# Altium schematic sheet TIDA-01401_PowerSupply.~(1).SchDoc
size 431 x 279 mm; Date: Not shown in title block; ApprovedBy: Not shown in title block; CheckedBy: Not shown in title block; Author: Not shown in title block; CompanyName: Not shown in title block; Engineer: Not shown in title block; Organization: Not shown in title block; Address1: Not shown in title block; Address2: Not shown in title block; Address3: Not shown in title block; Address4: Not shown in title block; DocumentNumber: 1; Revision: Use project parameter SCH_Rev; SheetNumber: 2; SheetTotal: 3; PageSetup: Record=PageOptions¦CenterHorizontal=True¦CenterVertical=True¦PrintScale=1.00¦XCorrection=1.00¦YCorrection=1.00¦PrintKind=0¦BorderSize=5000000¦LeftOffset=0¦BottomOffset=0¦Orientation=2¦PaperLength=1000¦PaperWidth=1000¦Scale=100¦PaperSource=15¦PrintQuality=600¦MediaType=1¦DitherType=10¦PaperKind=Letter¦PrintScaleMode=1
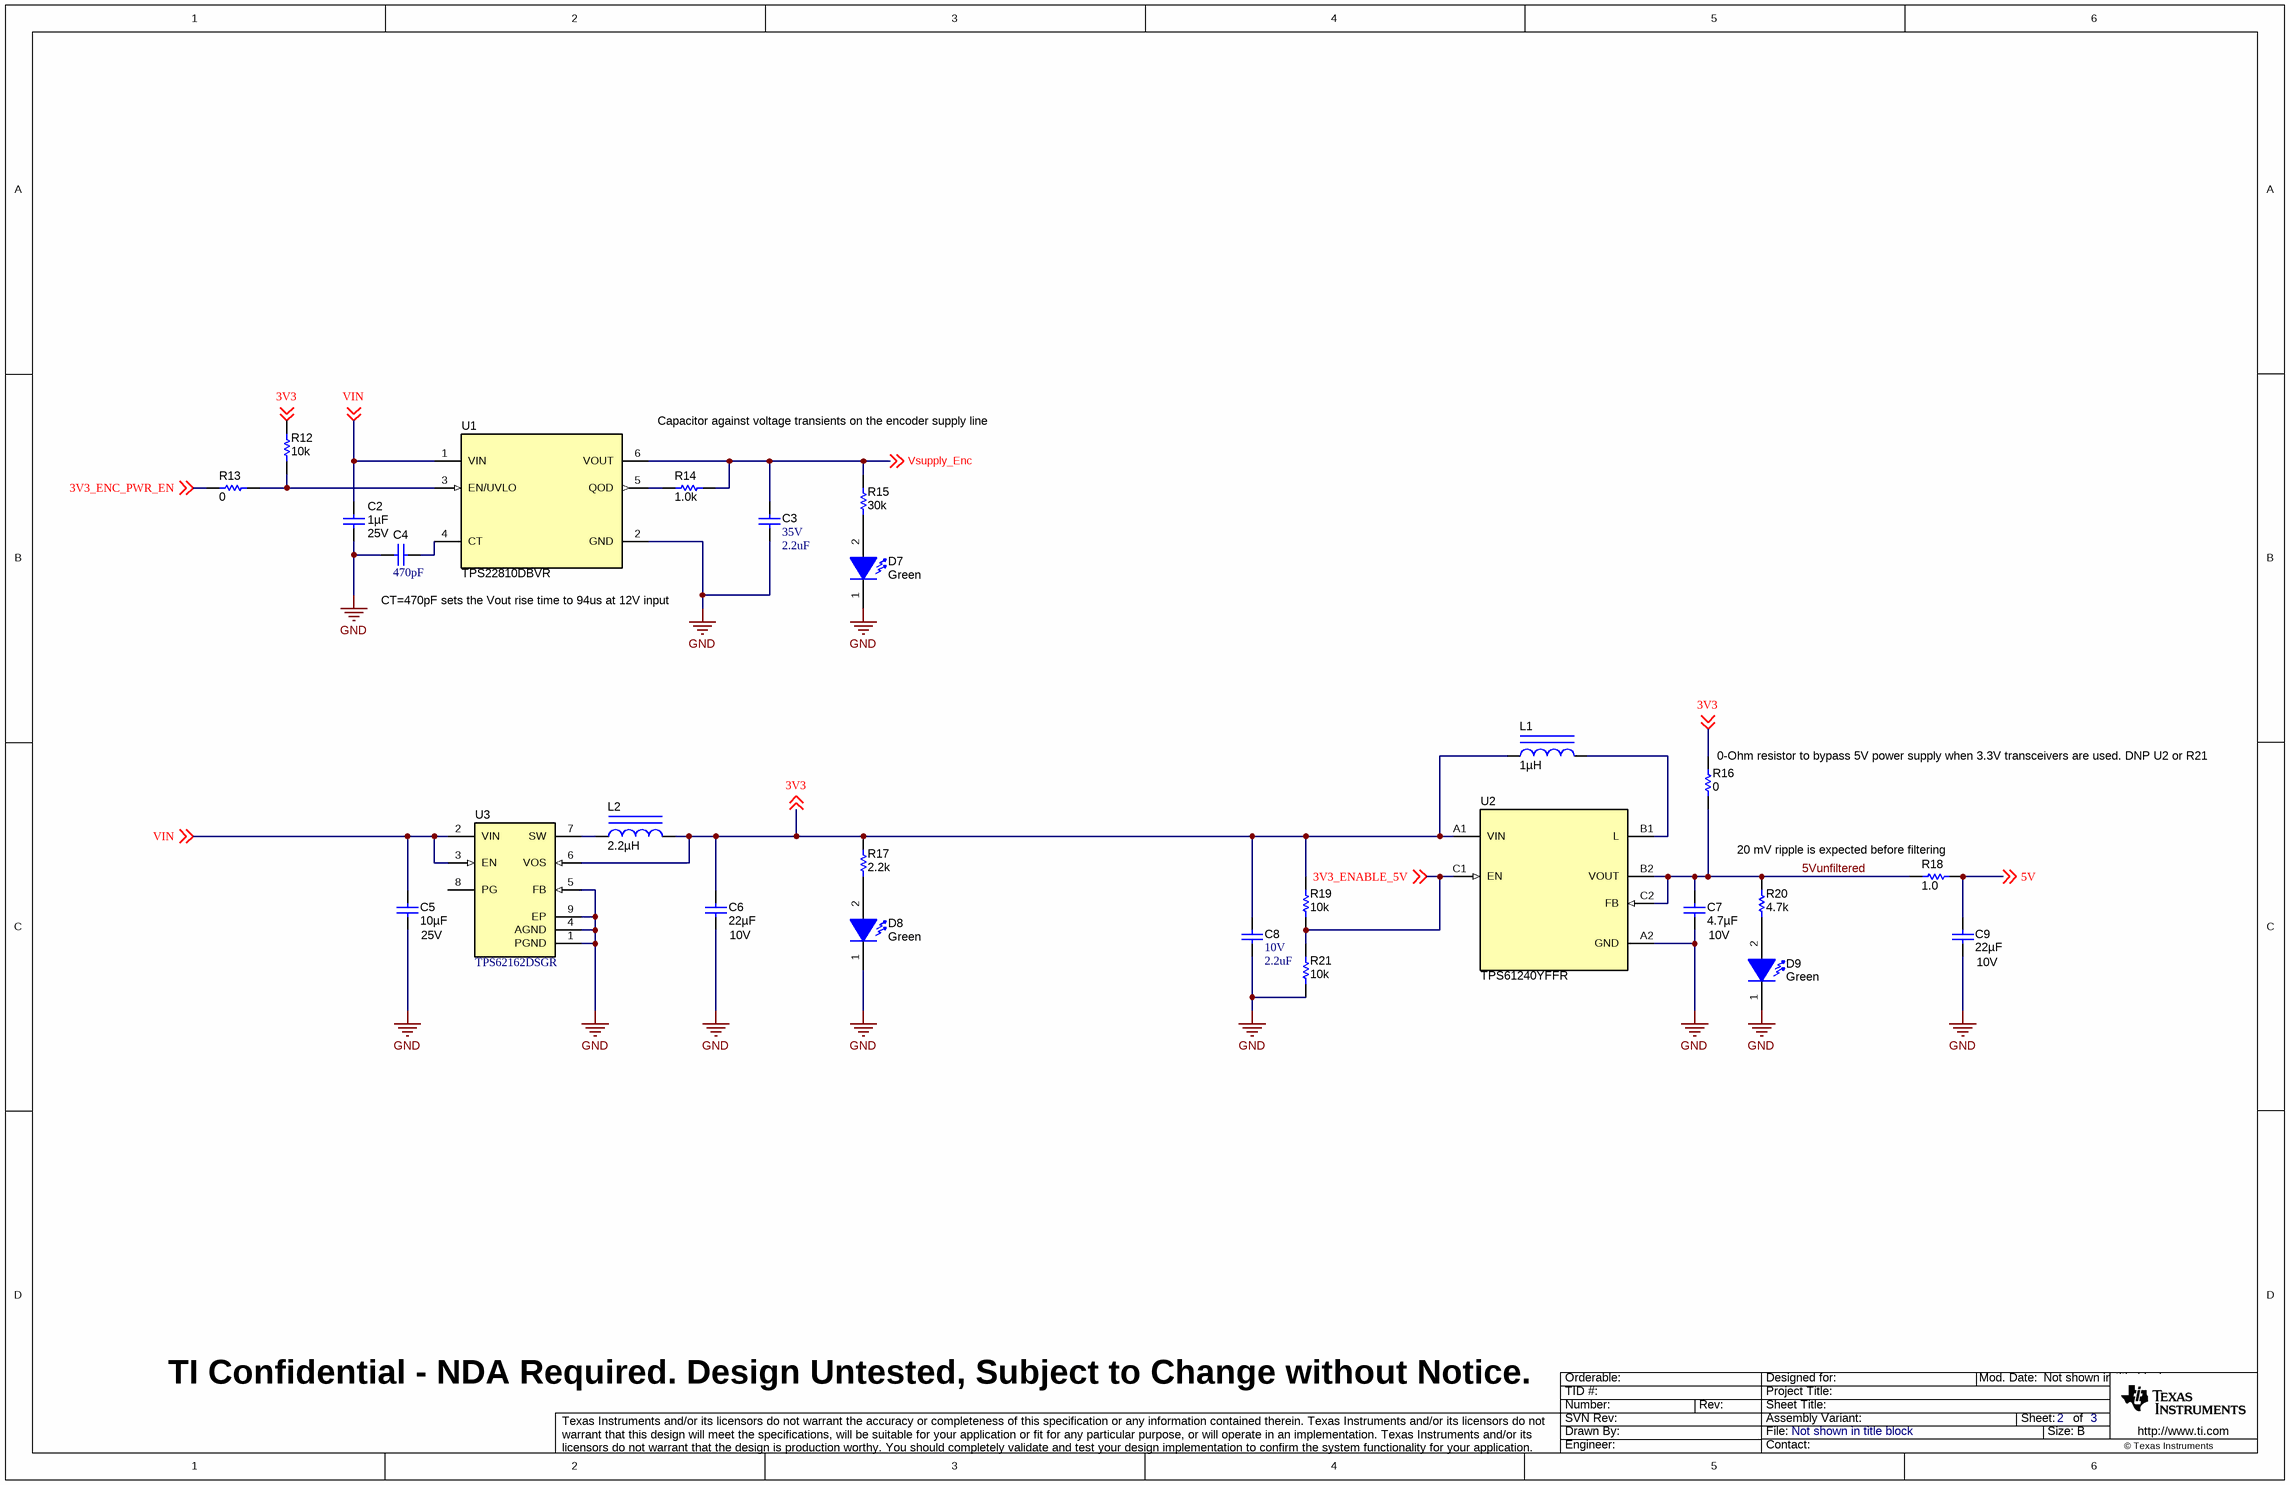
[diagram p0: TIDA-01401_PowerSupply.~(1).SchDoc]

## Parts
C2  ValueDisplayed: 1µF  Value2: 25V  [0603S]  (hidden comment: 885012206076)
C3  VDC_V: 35V  ValueDisplayed: 2.2uF  [0402_070]  (hidden comment: GRM155R6YA225ME11D)
C4  ValueDisplayed: 470pF  [0402S]  (hidden comment: GRM155R71H471KA01D)
C5  ValueDisplayed: 10µF  Value2: 25V  [0603S]  (hidden comment: C1608X5R1E106M080AC)
C6  ValueDisplayed: 22µF  Value2: 10V  [0603S]  (hidden comment: GRM187R61A226ME15D)
C7  ValueDisplayed: 4.7µF  Value2: 10V  [0402S]  (hidden comment: C1005X5R1A475K050BC)
C8  VDC_V: 10V  ValueDisplayed: 2.2uF  [0402S]  (hidden comment: 885012105013)
C9  ValueDisplayed: 22µF  Value2: 10V  [0603S]  (hidden comment: GRM187R61A226ME15D)
D7  value Green  [WL-SMCW_GREEN]  (hidden comment: 150060GS75000)
D8  value Green  [WL-SMCW_GREEN]  (hidden comment: 150060GS75000)
D9  value Green  [WL-SMCW_GREEN]  (hidden comment: 150060GS75000)
L1  ValueDisplayed: 1µH  [WE-PMI-0805_1]  (hidden comment: 74479775210)
L2  ValueDisplayed: 2.2µH  [XFL3012]  (hidden comment: XFL3012-222MEB)
R12  ValueDisplayed: 10k  [0402]  (hidden comment: CRCW040210K0JNED)
R13  ValueDisplayed: 0  [0402]  (hidden comment: CRCW04020000Z0ED)
R14  ValueDisplayed: 1.0k  [0603S]  (hidden comment: CRCW06031K00JNEA)
R15  ValueDisplayed: 30k  [0402S]  (hidden comment: CRCW040230K0JNED)
R16  ValueDisplayed: 0  [0402]  (hidden comment: CRCW04020000Z0ED)
R17  ValueDisplayed: 2.2k  [0402S]  (hidden comment: CRCW04022K20JNED)
R18  ValueDisplayed: 1.0  [0603S]  (hidden comment: CRCW06031R00JNEA)
R19  ValueDisplayed: 10k  [0402]  (hidden comment: CRCW040210K0JNED)
R20  ValueDisplayed: 4.7k  [0402S]  (hidden comment: CRCW04024K70JNED)
R21  ValueDisplayed: 10k  [0402]  (hidden comment: CRCW040210K0JNED)
U1  TPS22810DBVR  [DBV0006A_N]
U2  TPS61240YFFR  [YFF0006AEAE]
U3  TPS62162DSGR  [DSG0008A]

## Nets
GND: C2.2 C3.2 C4.1 C5.2 C6.2 C7.2 C8.2 C9.2 D7.1(K) D8.1(K) D9.1(K) R21.1 U1.2(GND) U2.A2(GND) U3.1(PGND) U3.4(AGND) U3.5(FB) U3.9(EP)
3V3: C6.1 C8.1 L1.1 L2.2 R12.2 R16.2 R17.2 R19.2 U2.A1(VIN) U3.6(VOS) ; off-sheet 3V3
3V3_ENABLE_5V: R19.1 R21.2 U2.C1(EN) ; off-sheet 3V3_ENABLE_5V
3V3_ENC_PWR_EN: R13.1 ; off-sheet 3V3_ENC_PWR_EN
5V: C9.1 R18.2 ; off-sheet 5V
5Vunfiltered: C7.1 R16.1 R18.1 R20.2 U2.B2(VOUT) U2.C2(FB)
VIN: C2.1 C5.1 U1.1(VIN) U3.2(VIN) U3.3(EN) ; off-sheet VIN
Vsupply_Enc: C3.1 R14.2 R15.1 U1.6(VOUT) ; off-sheet Vsupply_Enc
NetC4_2: C4.2 U1.4(CT)
NetD7_2: D7.2(A) R15.2
NetD8_2: D8.2(A) R17.1
NetD9_2: D9.2(A) R20.1
NetL1_2: L1.2 U2.B1(L)
NetL2_1: L2.1 U3.7(SW)
NetR12_1: R12.1 R13.2 U1.3(EN/UVLO)
NetR14_1: R14.1 U1.5(QOD)

Not connected (* = marked no-connect by the designer): U3 8(PG)

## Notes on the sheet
- (near U1) Capacitor against voltage transients on the encoder supply line
- CT=470pF sets the Vout rise time to 94us at 12V input
- (near R16) 0-Ohm resistor to bypass 5V power supply when 3.3V transceivers are used. DNP U2 or R21
- 20 mV ripple is expected before filtering
- TI Confidential - NDA Required. Design Untested, Subject to Change without Notice.

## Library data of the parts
C2 = 885012206076: CAP, CERM, 1 µF, 25 V, +/- 10%, X7R, 0603; Manufacturer: Wurth Elektronik; Polarized: N; CompType: Capacitor; Value: 1uF; U/M: EA; Cap_F: 0.000001; Tolerance_%: 10; Value1: Unknown; VDC_V: 25; TaMin_C: -55; TaMax_C: 125; Cap_Case: 0603; SizeArea_mm2: 1.28; SizeAreaWB_mm2: 4.68; SizeX_mm: 1.6; SizeY_mm: 0.8; SizeZ_mm: 1; AEC Category: Q200
C3 = CMP-0006621-2: CAP, CERM, 2.2 uF, 35 V, +/- 20%, X5R, 0402; Manufacturer: MuRata; TaMin_C: -55°C; Polarized: N; SizeAreaWB_mm2: 3; Value1: Unknown; U/M: EA; Value: 2.2uF; TaMax_C: 85°C; SizeZ_mm: 0.7; SizeX_mm: 1; SizeY_mm: 0.5; Cap_Case: 0402; CompType: Capacitor; Cap_F: 2.2µF; AEC Category: Q200
C4 = CMP-0006691-2: CAP, CERM, 470 pF, 50 V, +/- 10%, X7R, 0402; Manufacturer: MuRata; TaMin_C: -55°C; Polarized: N; SizeAreaWB_mm2: 3; Value1: Unknown; U/M: EA; Value: 470pF; TaMax_C: 125°C; SizeZ_mm: 0.6; SizeX_mm: 1; SizeY_mm: 0.5; Cap_Case: 0402; Value2: 50V; CompType: Capacitor; AEC Category: Q200
C5 = C1608X5R1E106M080AC: CAP, CERM, 10 µF, 25 V, +/- 20%, X5R, 0603; Manufacturer: TDK; Polarized: N; CompType: Capacitor; Value: 10uF; U/M: EA; Cap_F: 0.00001; Tolerance_%: 20; ESR_ohm: 0.004639; Value1: 0.004639 ohm; VDC_V: 25; IRMS_A: 2.41407; TaMin_C: -55; TaMax_C: 85; Cap_Case: 0603; SizeArea_mm2: 1.28; SizeAreaWB_mm2: 4.68; SizeX_mm: 1.6; SizeY_mm: 0.8; SizeZ_mm: 1; AEC Category: Q200
C6 C9 = GRM187R61A226ME15D: CAP, CERM, 22 µF, 10 V, +/- 20%, X5R, 0603; Manufacturer: MuRata; Polarized: N; CompType: Capacitor; Value: 22uF; U/M: EA; Cap_F: 0.000022; Tolerance_%: 20; Value1: Unknown; VDC_V: 10; TaMin_C: -55; TaMax_C: 85; Cap_Case: 0603; SizeArea_mm2: 1.28; SizeAreaWB_mm2: 4.68; SizeX_mm: 1.6; SizeY_mm: 0.8; SizeZ_mm: 1; AEC Category: Q200
C7 = C1005X5R1A475K050BC: CAP, CERM, 4.7 µF, 10 V, +/- 10%, X5R, 0402; Manufacturer: TDK; Polarized: N; CompType: Capacitor; Value: 4.7uF; U/M: EA; Cap_F: 0.0000047; Tolerance_%: 10; ESR_ohm: 0.003417; Value1: 0.003417 ohm; IRMS_A: 2.7063; TaMin_C: -55; TaMax_C: 85; Cap_Case: 0402_065; SizeArea_mm2: 0.5; SizeAreaWB_mm2: 3; SizeX_mm: 1; SizeZ_mm: 0.65; AEC Category: Q200
C8 = CMP-0006222-2: CAP, CERM, 2.2 uF, 10 V, +/- 20%, X5R, 0402; Manufacturer: Wurth Elektronik; TaMin_C: -55°C; Polarized: N; SizeAreaWB_mm2: 3; Value1: Unknown; U/M: EA; Value: 2.2uF; TaMax_C: 85°C; SizeZ_mm: 0.6; SizeX_mm: 1; SizeY_mm: 0.5; Cap_Case: 0402; CompType: Capacitor; Cap_F: 2.2µF; AEC Category: Q200
D7-D9 = 150060GS75000: LED, Green, SMD; Manufacturer: Wurth Elektronik; Type: InGaN; Vf_V: 3.2; Value2: 3.2V; Io_A: 0.02; Tjmax_C: 85; Value1: W; Angle: 140; U/M: EA
L1 = 74479775210: Inductor, Shielded Drum Core, Metal Composite, 1 µH, 0.7 A, 0.1 ohm, SMD; Manufacturer: Wurth Elektronik; Value: 1uH; Ind_H: 1.0E-6; Imax_A: 0.7; Irms: 1.1A @ 40C rise; Isat: 0.7A @ 30% inductance drop; DCR_ohm: 0.1; Value1: 0.1 ohm; Value2: 0.7A; SizeAreaWB_mm2: 6.6; SizeArea_mm2: 2.4; SizeX_mm: 2; SizeY_mm: 1.2; SizeZ_mm: 1; AEC Category: Q200
L2 = XFL3012-222MEB: Inductor, Shielded, Composite, 2.2 µH, 1.6 A, 0.08 ohm, SMD; Manufacturer: Coilcraft; Value: 2.2uH; Ind_H: 2.2E-6; Imax_A: 1.6; Irms: 1.9A @ 40C rise; Isat: 1.6A @ 30% inductance drop; DCR_ohm: 0.08; Value2: 1.6A; SizeAreaWB_mm2: 16; SizeArea_mm2: 9; SizeX_mm: 3; SizeZ_mm: 1.2; AEC Category: Q200
R12 R19 R21 = CRCW040210K0JNED: RES, 10 k, 5%, 0.063 W, 0402; Manufacturer: Vishay-Dale; CompType: Resistor; Value: 10k; Res_ohm: 10000; Value_Code: 10k0; Tolerance_%: 5; Power_W: 0.063; Value2: 0.063W; VDC_V: 50; TempCo: 200 ppm/C; SizeArea_mm2: 0.5; SizeX_mm: 1; SizeZ_mm: 0.6; EIA_Code: E24; U/M: EA; AEC Category: Q200
R13 R16 = CRCW04020000Z0ED: RES, 0, 5%, 0.063 W, 0402; Manufacturer: Vishay-Dale; CompType: Resistor; Value: 0; Value_Code: 0000; Tolerance_%: 5; Power_W: 0.063; Value2: 0.063W; VDC_V: 50; TempCo: 200 ppm/C; SizeArea_mm2: 0.5; SizeX_mm: 1; SizeZ_mm: 0.6; EIA_Code: E24; U/M: EA; AEC Category: Q200
R14 = CRCW06031K00JNEA: RES, 1.0 k, 5%, 0.1 W, 0603; Manufacturer: Vishay-Dale; CompType: Resistor; Value: 1.0k; Res_ohm: 1000; Value_Code: 1k00; Tolerance_%: 5; Power_W: 0.1; Value2: 0.1W; VDC_V: 75; TempCo: 200 ppm/C; SizeArea_mm2: 1.28; SizeX_mm: 1.6; SizeY_mm: 0.8; SizeZ_mm: 1; EIA_Code: E24; U/M: EA; AEC Category: Q200
R15 = CRCW040230K0JNED: RES, 30 k, 5%, 0.063 W, 0402; Manufacturer: Vishay-Dale; CompType: Resistor; Value: 30k; Res_ohm: 30000; Value_Code: 30k0; Tolerance_%: 5; Power_W: 0.063; Value2: 0.063W; VDC_V: 50; TempCo: 200 ppm/C; SizeArea_mm2: 0.5; SizeX_mm: 1; SizeZ_mm: 0.6; EIA_Code: E24; U/M: EA; AEC Category: Q200
R17 = CRCW04022K20JNED: RES, 2.2 k, 5%, 0.063 W, 0402; Manufacturer: Vishay-Dale; CompType: Resistor; Value: 2.2k; Res_ohm: 2200; Value_Code: 2k20; Tolerance_%: 5; Power_W: 0.063; Value2: 0.063W; VDC_V: 50; TempCo: 200 ppm/C; SizeArea_mm2: 0.5; SizeX_mm: 1; SizeZ_mm: 0.6; EIA_Code: E24; U/M: EA; AEC Category: Q200
R18 = CRCW06031R00JNEA: RES, 1.0, 5%, 0.1 W, 0603; Manufacturer: Vishay-Dale; CompType: Resistor; Value: 1.0; Res_ohm: 1; Value_Code: 1R00; Tolerance_%: 5; Power_W: 0.1; Value2: 0.1W; VDC_V: 75; TempCo: 200 ppm/C; SizeArea_mm2: 1.28; SizeX_mm: 1.6; SizeY_mm: 0.8; EIA_Code: E24; U/M: EA; AEC Category: Q200
R20 = CRCW04024K70JNED: RES, 4.7 k, 5%, 0.063 W, 0402; Manufacturer: Vishay-Dale; CompType: Resistor; Value: 4.7k; Res_ohm: 4700; Value_Code: 4k70; Tolerance_%: 5; Power_W: 0.063; Value2: 0.063W; VDC_V: 50; TempCo: 200 ppm/C; SizeArea_mm2: 0.5; SizeX_mm: 1; SizeZ_mm: 0.6; EIA_Code: E24; U/M: EA; AEC Category: Q200
U1 = TPS22810DBVR: 2.7-18-V, 2-A, 79-mΩ On-Resistance Load Switch with Thermal Protection, DBV0006A (SOT-23-6); Alternate PartNumber: TPS22810DBVT; Manufacturer: Texas Instruments; SymbolCreator: Altium; SizeArea_mm2: 8.12; SizeAreaWB_mm2: 14.82; SizeX_mm: 2.8; SizeY_mm: 2.9; SizeZ_mm: 1.45; CompType: IC; U/M: EA
U2 = TPS61240YFFR: 3.5-MHz High Efficiency Step-Up Converter, YFF0006AEAE (DSBGA-6); Alternate PartNumber: TPS61240YFFT; Manufacturer: Texas Instruments; SymbolCreator: Altium; SizeArea_mm2: 1.076848; SizeAreaWB_mm2: 4.190848; SizeX_mm: 0.856; SizeY_mm: 1.258; SizeZ_mm: 0.625; CompType: IC; U/M: EA
U3 = TPS62162DSGR: Buck Step Down Regulator with 3 to 17 V Input and 3.3 V Output, -40 to 85 degC, 8-Pin WSON (DSG), Green (RoHS & no Sb/Br); Manufacturer: Texas Instruments; Alternate PartNumber: Equivalent; Duty Cycle(Max)(%): 100; Iout(Max)(A): 1; Iq(Typ)(mA): 0.017; Preset Vout(V): 3.3; Rating: Catalog; SubFamily: Step-Down Regulator; Switch Current Limit(Typ)(A): 1.8; Synchronous Rectification: TRUE; Vin(Max)(V): 17; Vin(Min)(V): 3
